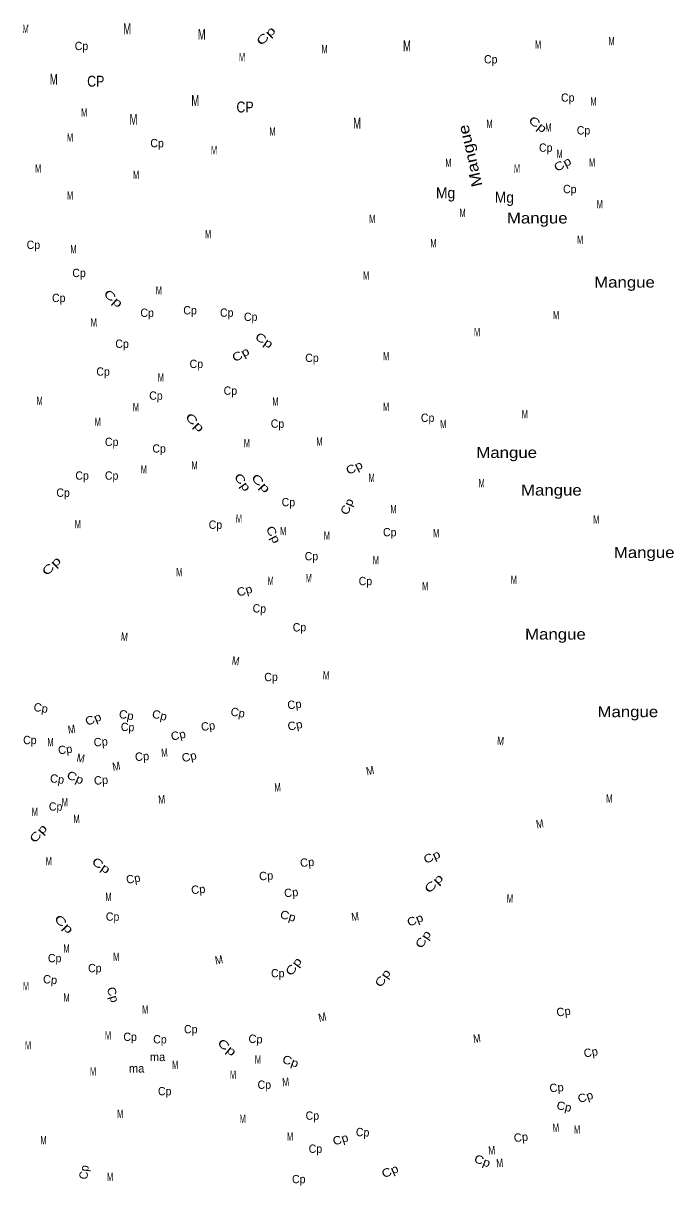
# Model space of a CAD drawing. Extents: x 713577 to 726626, y 7177731 to 7191794.
# Drawn here: x 723647 to 726626, y 7186343 to 7191662 of the extents above; entities that cross this region are included whole.
import ezdxf
from ezdxf.enums import TextEntityAlignment as Align

# ---------------------------------------------------------------- set-up
doc = ezdxf.new("R2010")
doc.units = 0
doc.header["$LTSCALE"] = 15
doc.layers.add('19', color=7, linetype='Continuous')

msp = doc.modelspace()

# ---------------------------------------------------------------- texts
at = {"layer": '19'}
for s, height, rotation, width, p in [('M', 38, 359.799, 0.65, (723658.54, 7191617.19)), ('M', 49.99, 359.812, 0.65, (724123.14, 7191612.29)), ('Cp', 38, 44.17, 1.5, (724771.84, 7191591.04)), ('M', 49.99, 359.812, 0.65, (724464.65, 7191586.64)), ('M', 38, 359.799, 0.65, (726340.98, 7191561.67)), ('Cp', 38, 359.799, 0.95, (723914.11, 7191539.35)), ('M', 38, 359.799, 0.65, (725027.14, 7191525.36)), ('M', 49.99, 359.812, 0.65, (725404.28, 7191534.05)), ('M', 38, 359.799, 0.65, (726004.68, 7191545.37)), ('M', 38, 359.799, 0.65, (724649.04, 7191488.3)), ('Cp', 38, 359.799, 0.95, (725787.89, 7191478.51)), ('M', 49.99, 359.812, 0.65, (723786.86, 7191380.88)), ('M', 49.99, 359.812, 0.65, (724434.99, 7191284.11)), ('Cp', 38, 359.799, 0.95, (726140.61, 7191303.26)), ('M', 38, 359.799, 0.65, (726258.33, 7191285.75)), ('M', 38, 359.799, 0.65, (723926.57, 7191235.41)), ('M', 49.99, 359.812, 0.65, (724152.36, 7191197.52)), ('M', 49.99, 359.812, 0.65, (725175.95, 7191180.07)), ('M', 38, 359.799, 0.65, (725782.29, 7191183.7)), ('Cp', 38, 322.328, 1.35, (725992.05, 7191184.41)), ('M', 38, 359.799, 0.65, (724788.35, 7191148.57)), ('Mangue', 50, 103.225, 1.2, (725717.55, 7191061.08)), ('M', 38, 359.799, 0.65, (726051.74, 7191166.26)), ('Cp', 38, 359.799, 0.95, (726212.65, 7191153.32)), ('M', 38, 359.799, 0.65, (723861.74, 7191120.5)), ('Cp', 38, 359.799, 0.95, (724260.13, 7191094.88)), ('Cp', 38, 359.799, 0.95, (726039.5, 7191074.14)), ('M', 38, 359.799, 0.65, (724520.83, 7191061.99)), ('M', 38, 359.799, 0.65, (726103.23, 7191046.18)), ('M', 38, 359.799, 0.65, (723715.61, 7190978.8)), ('M', 38, 359.799, 0.65, (725594.09, 7191005.24)), ('M', 38, 359.799, 0.65, (725908.08, 7190978.6)), ('Cp', 38, 28.418, 1.25, (726125.7, 7191000.91)), ('M', 38, 359.799, 0.65, (726252.07, 7191005.7)), ('M', 38, 359.799, 0.65, (724164, 7190949.95)), ('M', 38, 359.799, 0.65, (723861.84, 7190855.61)), ('Cp', 38, 359.799, 0.95, (726149.7, 7190884.61)), ('M', 38, 359.799, 0.65, (726287.07, 7190815.3)), ('M', 38, 359.799, 0.65, (725658.99, 7190775.27)), ('M', 38, 359.799, 0.65, (725245.43, 7190747.76)), ('M', 38, 359.799, 0.65, (724493.72, 7190678.78)), ('M', 38, 359.799, 0.65, (726197.38, 7190652.94)), ('Cp', 38, 359.799, 0.95, (723693.98, 7190629.48)), ('M', 38, 359.799, 0.65, (723877.43, 7190609.18)), ('M', 38, 359.799, 0.65, (725525.54, 7190636.58)), ('Cp', 38, 359.799, 0.95, (723902.85, 7190500.71)), ('M', 38, 359.799, 0.65, (725217.46, 7190488.8)), ('Cp', 38, 359.799, 0.95, (723810.03, 7190386.35)), ('Cp', 38, 318.984, 1.45, (724047.6, 7190388.62)), ('M', 38, 359.799, 0.65, (724268.44, 7190421.06)), ('Cp', 38, 359.799, 0.95, (724411.02, 7190329.94)), ('M', 38, 2.43, 0.7, (723971.42, 7190274.12)), ('Cp', 38, 359.799, 0.95, (724214.7, 7190318.51)), ('Cp', 38, 359.799, 0.95, (724578.99, 7190319.19)), ('Cp', 38, 359.799, 0.95, (724688.64, 7190299.97)), ('M', 38, 359.799, 0.65, (726087.04, 7190308.2)), ('M', 38, 359.799, 0.65, (725725.07, 7190230.37)), ('Cp', 38, 359.799, 0.95, (724099.89, 7190176.77)), ('Cp', 38, 326.372, 1.3, (724740.32, 7190195.83)), ('Cp', 38, 29.181, 1.25, (724652.15, 7190130.48)), ('Cp', 38, 359.799, 0.95, (724969.28, 7190112.15)), ('M', 38, 359.799, 0.65, (725309.09, 7190119.57)), ('Cp', 38, 359.799, 0.95, (724439.9, 7190084.65)), ('Cp', 38, 359.799, 0.95, (724012.98, 7190049.4)), ('M', 38, 359.799, 0.65, (724277.67, 7190022.84)), ('Cp', 38, 359.799, 0.95, (724595.68, 7189962.2)), ('M', 38, 359.799, 0.65, (723722.52, 7189915.82)), ('Cp', 38, 359.799, 0.95, (724254.94, 7189939.44)), ('M', 38, 359.799, 0.65, (724801.95, 7189912.39)), ('M', 38, 359.799, 0.65, (724163.43, 7189886.86)), ('M', 38, 359.799, 0.65, (725308.56, 7189888.13)), ('M', 38, 359.799, 0.65, (725944.01, 7189854.1)), ('M', 38, 359.799, 0.65, (723988.43, 7189819.28)), ('Cp', 38, 313.942, 1.5, (724419.97, 7189822.71)), ('Cp', 38, 359.799, 0.95, (724811.58, 7189811.07)), ('Cp', 38, 359.799, 0.95, (725498.83, 7189838.02)), ('M', 38, 2.195, 0.7, (725571.65, 7189809.72)), ('Cp', 38, 359.799, 0.95, (724052.3, 7189727.5)), ('Cp', 38, 359.799, 0.95, (724269.68, 7189697.42)), ('M', 38, 359.799, 0.65, (724671.25, 7189722.42)), ('M', 38, 359.799, 0.65, (725003.4, 7189729.03)), ('M', 38, 359.799, 0.65, (724199.44, 7189601.98)), ('M', 38, 359.799, 0.65, (724431.83, 7189620.36)), ('Cp', 38, 26.401, 1.2, (725171.38, 7189612.04)), ('Cp', 38, 359.799, 0.95, (723917.04, 7189573.58)), ('Cp', 38, 359.799, 0.95, (724052.13, 7189573.48)), ('Cp', 38, 305.647, 1.35, (724636.15, 7189551.19)), ('Cp', 38, 313.614, 1.5, (724721.8, 7189544.25)), ('M', 38, 359.799, 0.65, (725242.57, 7189563.29)), ('M', 38, 359.799, 0.65, (725746.2, 7189539.11)), ('Cp', 38, 359.799, 0.95, (723829.93, 7189495.21)), ('Cp', 38, 359.799, 0.95, (724861.33, 7189451.93)), ('Cp', 38, 67.79, 1.15, (725147.47, 7189443.51)), ('M', 38, 359.799, 0.65, (725342.51, 7189420.05)), ('M', 38, 359.799, 0.65, (724635.21, 7189376.69)), ('M', 38, 359.799, 0.65, (723897.35, 7189350.83)), ('Cp', 38, 359.799, 0.95, (724527.5, 7189348.77)), ('Cp', 38, 297.473, 1.25, (724776.03, 7189314)), ('M', 38, 359.799, 0.65, (724837.85, 7189319.76)), ('Cp', 38, 359.799, 0.95, (725325.4, 7189314.58)), ('M', 38, 359.799, 0.65, (725037.77, 7189299.03)), ('M', 38, 359.799, 0.65, (725538.23, 7189309.65)), ('Cp', 38, 44.582, 1.5, (723789.68, 7189165)), ('Cp', 38, 359.799, 0.95, (724966.89, 7189204.63)), ('M', 38, 359.799, 0.65, (725262.18, 7189186.56)), ('M', 38, 359.799, 0.65, (724361.93, 7189131.61)), ('M', 38, 359.799, 0.65, (724954.28, 7189104.41)), ('Cp', 38, 16.632, 1.1, (724665.86, 7189048.13)), ('M', 38, 359.799, 0.65, (724780.19, 7189092.45)), ('Cp', 38, 359.799, 0.95, (725214.01, 7189090.76)), ('M', 38, 359.799, 0.65, (725487.76, 7189067.39)), ('M', 38, 359.799, 0.65, (725893.83, 7189097.05)), ('Cp', 38, 357.833, 0.95, (724727.83, 7188965.44)), ('M', 38, 355.312, 0.75, (724109.34, 7188835.95)), ('Cp', 38, 1.411, 0.95, (724912.54, 7188879.42)), ('M', 38, 351.851, 0.8, (724617.67, 7188725.88)), ('Cp', 38, 1.284, 0.95, (724782.3, 7188651.84)), ('M', 38, 356.679, 0.7, (725032.89, 7188659.13)), ('Cp', 38, 21.873, 1.15, (723974.68, 7188460.64)), ('Cp', 38, 348.69, 1.05, (724116.11, 7188478.21)), ('Cp', 38, 347.233, 1.05, (724267.57, 7188477.52)), ('M', 38, 9.187, 0.8, (723872.09, 7188412.82)), ('Cp', 38, 357.699, 0.95, (724124.59, 7188422.97)), ('Cp', 38, 11.583, 1.05, (724895.3, 7188431.38)), ('Cp', 38, 359.988, 0.95, (723677.96, 7188363.28)), ('Cp', 38, 12.651, 1.05, (724361.33, 7188386.52)), ('M', 38, 355.593, 0.75, (725831.52, 7188359.56)), ('M', 38, 359.988, 0.65, (723772.41, 7188353.35)), ('M', 38, 3.764, 0.7, (724295.24, 7188305.84)), ('M', 38, 349.109, 0.85, (723907.35, 7188280.52)), ('Cp', 38, 13.164, 1.05, (724411.22, 7188288.03)), ('Cp', 38, 336.437, 1.2, (723878.56, 7188193.43)), ('M', 38, 10.52, 0.85, (724076.98, 7188243.72)), ('M', 38, 11.019, 0.85, (725238.91, 7188224.12)), ('M', 38, 2.279, 0.7, (724812.7, 7188146.79)), ('M', 38, 4.673, 0.75, (724283.18, 7188091.72)), ('M', 38, 358.954, 0.7, (726330.45, 7188095.26)), ('Cp', 38, 359.988, 0.95, (723795.79, 7188059.1)), ('M', 38, 359.988, 0.65, (723838.07, 7188078.57)), ('M', 38, 359.988, 0.65, (723700.35, 7188034.68)), ('M', 38, 1.164, 0.7, (723891.9, 7188002.88)), ('M', 38, 9.914, 0.8, (726015.95, 7187980.32)), ('Cp', 38, 49.395, 1.4, (723730.63, 7187942.38)), ('Cp', 38, 24.437, 1.2, (725526.05, 7187830.91)), ('M', 38, 359.988, 0.65, (723764.37, 7187809.11)), ('Cp', 38, 325.381, 1.35, (723993.89, 7187792.75)), ('Cp', 38, 46.065, 1.5, (725540.52, 7187712.89)), ('M', 38, 359.988, 0.65, (724037.78, 7187645.57)), ('M', 38, 356.935, 0.7, (725874.57, 7187638.18)), ('Cp', 38, 345.141, 1.1, (724854.89, 7187559.1)), ('M', 38, 7.966, 0.8, (725169.67, 7187555.31)), ('Cp', 38, 315, 1.5, (723820.44, 7187526.79)), ('Cp', 38, 359.988, 0.95, (724056.58, 7187555.41)), ('Cp', 38, 22.507, 1.15, (725448.67, 7187541.7)), ('Cp', 38, 56.824, 1.3, (725494.06, 7187460.09)), ('M', 38, 359.988, 0.65, (723845.52, 7187409.16)), ('Cp', 38, 359.988, 0.95, (723791.33, 7187365.27)), ('M', 38, 359.988, 0.65, (724073.42, 7187371.09)), ('M', 38, 10.594, 0.85, (724546.84, 7187357.58)), ('Cp', 38, 359.988, 0.95, (723975.26, 7187319.65)), ('Cp', 38, 359.968, 0.95, (724812.93, 7187296.28)), ('Cp', 38, 54.842, 1.35, (724900.81, 7187334.99)), ('Cp', 38, 56.283, 1.3, (725309, 7187282.37)), ('M', 38, 359.988, 0.65, (723660.12, 7187237.18)), ('M', 38, 359.988, 0.65, (723846.12, 7187184.42)), ('Cp', 38, 287.974, 1.1, (724040.3, 7187211.32)), ('M', 38, 359.988, 0.65, (724206.13, 7187129.98)), ('M', 38, 12.276, 0.85, (725020.91, 7187095.69)), ('Cp', 38, 359.988, 0.95, (724414.43, 7187040.17)), ('M', 38, 359.988, 0.65, (724035.7, 7187011.79)), ('Cp', 38, 359.988, 0.95, (724137.02, 7187005.22)), ('Cp', 38, 359.988, 0.95, (724273.41, 7186993.97)), ('Cp', 38, 321.215, 1.4, (724568.96, 7186961.45)), ('M', 38, 7.633, 0.8, (725727.21, 7186998.1)), ('M', 38, 359.988, 0.65, (723669.44, 7186966.29)), ('M', 38, 359.988, 0.65, (724343.13, 7186876.98)), ('Cp', 38, 340.537, 1.15, (724865.16, 7186894.39)), ('M', 38, 359.988, 0.65, (723966.97, 7186847.01)), ('M', 38, 359.988, 0.65, (724607.98, 7186831.68)), ('Cp', 38, 359.988, 0.95, (724751.23, 7186786.14)), ('M', 38, 5.514, 0.75, (724850.98, 7186799.14)), ('Cp', 38, 359.988, 0.95, (724295.15, 7186756.51)), ('Cp', 38, 18.42, 1.1, (726227.13, 7186731.49)), ('M', 38, 359.988, 0.65, (724091.76, 7186653.45)), ('Cp', 38, 347.677, 1.05, (726120.07, 7186687)), ('M', 38, 359.988, 0.65, (724652.19, 7186630.22)), ('M', 38, 359.988, 0.65, (724869.14, 7186549.26)), ('Cp', 38, 357.33, 0.95, (725200.56, 7186568.76)), ('M', 38, 3.806, 0.7, (726087.78, 7186589.26)), ('M', 38, 359.988, 0.65, (726183.05, 7186580.62)), ('M', 38, 359.988, 0.65, (723740.35, 7186531.67)), ('Cp', 38, 359.988, 0.95, (724985.31, 7186493.16)), ('Cp', 38, 17.729, 1.1, (725105.63, 7186537.25)), ('Cp', 38, 339.16, 1.15, (725743.13, 7186438.87)), ('M', 38, 5.313, 0.75, (725794.59, 7186485.91)), ('Cp', 38, 23.569, 1.2, (725334.32, 7186392.06)), ('M', 38, 4.945, 0.75, (725830.76, 7186427.79)), ('M', 38, 359.988, 0.65, (724045.14, 7186363.84)), ('Cp', 38, 359.988, 0.95, (724909, 7186354.14))]:
    msp.add_text(s, height=height, rotation=rotation, dxfattribs=dict(at, width=width)).set_placement(p, align=Align.CENTER)
for s, height, width, p in [('CP', 50, 0.85, (723979.59, 7191372.16)), ('CP', 50, 0.85, (724663.06, 7191254.05)), ('Mg', 50, 0.95, (725581.18, 7190861.28)), ('Mg', 50, 0.95, (725850.31, 7190841.06)), ('Mangue', 50, 1.15, (726000.94, 7190746.09)), ('Mangue', 50, 1.15, (726400.36, 7190452.6)), ('Mangue', 50, 1.15, (725860.84, 7189673.12)), ('Mangue', 50, 1.15, (726065.49, 7189501.17)), ('M', 38, 0.65, (726271.11, 7189371.96)), ('Mangue', 50, 1.15, (726490.35, 7189215.88)), ('Mangue', 50, 1.15, (726084.09, 7188842.05)), ('Mangue', 50, 1.15, (726415.56, 7188486.95)), ('M', 38, 0.65, (724722.18, 7186901.88)), ('Cp', 38, 0.95, (724971.1, 7186644.63))]:
    msp.add_text(s, height=height, dxfattribs=dict(at, width=width)).set_placement(p, align=Align.CENTER)
for s, rotation, p in [('Cp', 350.225, (723724.97, 7188510.71)), ('Cp', 6.863, (724891.41, 7188526.21)), ('Cp', 349.908, (724626.66, 7188489.4)), ('Cp', 7.42, (724495.98, 7188427.49)), ('Cp', 5.292, (724003.99, 7188355.04)), ('Cp', 7.718, (723841.8, 7188320.29)), ('Cp', 4.692, (724192.86, 7188288.4)), ('Cp', 352.203, (723800.24, 7188185.41)), ('Cp', 4.337, (724004.97, 7188179.67)), ('Cp', 5.198, (724949.06, 7187803.74)), ('Cp', 9.927, (724154.27, 7187729.21)), ('Cp', 3.783, (724761.03, 7187742.06)), ('Cp', 5.601, (724450.52, 7187679.81)), ('Cp', 5.998, (724876.14, 7187665.53)), ('Cp', 354.474, (723768.81, 7187267.38)), ('Cp', 7.871, (726123.45, 7187121.03)), ('Cp', 356.234, (724709.88, 7186995.52)), ('Cp', 10.503, (726249.21, 7186934.9)), ('ma', 359.988, (724262.56, 7186912.99)), ('ma', 359.988, (724166.77, 7186860.83)), ('Cp', 5.609, (726090.93, 7186772.92)), ('Cp', 6.463, (725927.93, 7186545.7)), ('Cp', 83.636, (723944.36, 7186402.35))]:
    msp.add_text(s, height=38, rotation=rotation, dxfattribs=at).set_placement(p, align=Align.CENTER)

doc.saveas('drawing.dxf')
